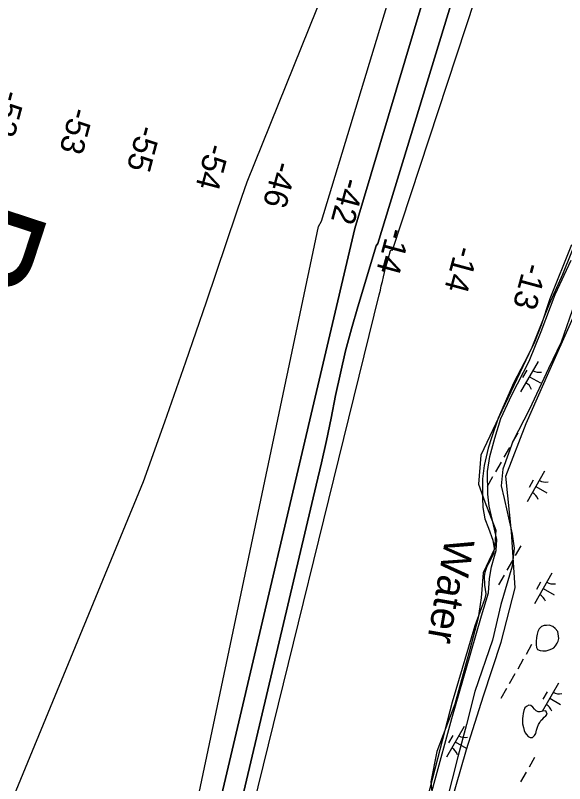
# Model space of a CAD drawing. Extents: x 3930721 to 3950824, y 220441 to 242861.
# Drawn here: x 3942447 to 3943227, y 233046 to 234136 of the extents above; entities that cross this region are included whole.
import ezdxf

# ---------------------------------------------------------------- set-up
doc = ezdxf.new("R2010")
doc.units = 0
for name, color, linetype in [('V-RIVR-EDGE', 7, 'Continuous'), ('V-RIVR-IDEN', 7, 'Continuous'), ('V-RIVR-JETY', 7, 'Continuous'), ('V-RIVR-RANG', 7, 'Continuous'), ('V-RRAP-FSHR', 7, 'Continuous'), ('V-TOPO-DPTH', 7, 'Continuous'), ('V-TOPO-MAJR', 7, 'Continuous'), ('V-TOPO-MINR', 7, 'Continuous'), ('V-TOPO-SHOR', 7, 'Continuous'), ('V-WETL-SWMP', 7, 'Continuous')]:
    doc.layers.add(name, color=color, linetype=linetype)

msp = doc.modelspace()

# ---------------------------------------------------------------- linework, layer by layer
at = {"layer": 'V-RIVR-EDGE'}
msp.add_lwpolyline([(3943285.6, 233921.8), (3943223.4, 233768.3), (3943204.5, 233725.8), (3943180.1, 233664.4), (3943107.7, 233511.7), (3943104.5, 233470.8), (3943113.2, 233445.6), (3943128.9, 233405.5), (3943127.3, 233378.7), (3943110.8, 233344.9), (3943108.4, 233309.4), (3943103.7, 233281.1), (3943091.9, 233236.2), (3943070.7, 233158.3), (3943045.5, 233091.4), (3943036.8, 233048.1), (3943039.2, 233024.5)], dxfattribs=at)
at = {"layer": 'V-RIVR-JETY'}
for points in [[(3943033.1, 233014.5), (3943041.4, 233046.4), (3943066.4, 233138.3), (3943093.4, 233231.4), (3943108.6, 233283.6), (3943118.4, 233316.3), (3943120.2, 233336.6), (3943122.8, 233353.3), (3943127.3, 233368.5), (3943129.4, 233376.3), (3943130.4, 233391.9), (3943125.6, 233413.1), (3943119.3, 233439.4), (3943117.5, 233456.6), (3943117.2, 233488.6), (3943120.6, 233510.1), (3943127.6, 233535.8), (3943136.1, 233563.8), (3943151.5, 233597.6), (3943176.3, 233645), (3943193.3, 233687.4), (3943213.1, 233739.9), (3943236.1, 233788.4)], [(3943241.1, 233728.1), (3943221.6, 233672.1), (3943203.9, 233634.8), (3943176.6, 233577), (3943153.3, 233531.2), (3943138.7, 233491.9), (3943136.4, 233468.1), (3943140.9, 233450.4), (3943144.9, 233431.6), (3943152.3, 233399.9), (3943154.8, 233379.9), (3943152.1, 233354.1), (3943136.2, 233300), (3943124.2, 233249.4), (3943099.4, 233176.6), (3943087.4, 233129.5), (3943075.1, 233083.9), (3943051.6, 232990.8)]]:
    msp.add_lwpolyline(points, dxfattribs=at)
at = {"layer": 'V-RRAP-FSHR'}
msp.add_lwpolyline([(3942882, 232404), (3942906.2, 232480.2), (3942929.5, 232556.7), (3942952.8, 232633.3), (3942976.5, 232709.8), (3942998.6, 232786.6), (3943020.8, 232863.4), (3943043, 232940.3), (3943065.2, 233017.2), (3943087.4, 233094.2), (3943111.4, 233170.3), (3943136.4, 233246.3), (3943156.6, 233323.6), (3943151.4, 233402.9), (3943143.4, 233482.1), (3943171.9, 233556.6), (3943204.4, 233629.7), (3943236.8, 233702.9), (3943268.8, 233776.2), (3943300.4, 233849.7), (3943331.9, 233923.2), (3943363.4, 233996.7), (3943394.9, 234070.3), (3943426.5, 234144)], dxfattribs=at)
at = {"layer": 'V-TOPO-DPTH'}
for points in [[(3942394.4, 231903.7), (3942586.2, 232551.5), (3942601, 232601.9), (3942615.5, 232652.3), (3942629.6, 232702.8), (3942643.5, 232753.3), (3942665.8, 232835.5), (3942668.3, 232845.1), (3942670.6, 232854.7), (3942672.5, 232864.3), (3942877.4, 233836.1), (3942881.5, 233844), (3943173.7, 234806.4)], [(3942394.4, 231903.7), (3942586.2, 232551.5), (3942601, 232601.9), (3942615.5, 232652.3), (3942629.6, 232702.8), (3942643.5, 232753.3), (3942665.8, 232835.5), (3942668.3, 232845.1), (3942670.6, 232854.7), (3942672.5, 232864.3), (3942877.4, 233836.1), (3942881.5, 233844), (3943173.7, 234806.4)], [(3943259.1, 234785.7), (3942961.5, 233812), (3942959.1, 233808.6), (3942933, 233722.4), (3942924, 233691.2), (3942915.7, 233659.8), (3942908.4, 233628.1), (3942901.7, 233596.3), (3942895.2, 233564.5), (3942888.6, 233532.6), (3942881.5, 233500.9), (3942874.2, 233469.2), (3942743, 232914.2), (3942734.1, 232877.2), (3942725, 232840.3), (3942715.6, 232803.4), (3942706, 232766.6), (3942520.9, 232068.2)], [(3942436.3, 231927), (3942493.1, 232113.6), (3942526.9, 232226.7), (3942560, 232340), (3942592, 232453.7), (3942623.2, 232567.6), (3942685.8, 232801.1), (3942691.8, 232824.3), (3942697.6, 232847.5), (3942702.9, 232870.9), (3942708, 232894.3), (3942929, 233833.4), (3943212.5, 234783.4)], [(3943212.5, 234783.4), (3942929, 233833.4), (3942708, 232894.3), (3942702.9, 232870.9), (3942697.6, 232847.5), (3942691.8, 232824.3), (3942685.8, 232801.1), (3942623.2, 232567.6), (3942592, 232453.7), (3942560, 232340), (3942526.9, 232226.7), (3942493.1, 232113.6), (3942436.3, 231927)]]:
    msp.add_lwpolyline(points, dxfattribs=at)
at = {"layer": 'V-TOPO-MAJR'}
msp.add_lwpolyline([(3942426.3, 232982), (3942628.9, 233474.4), (3942659.3, 233559.1), (3942689, 233644.1), (3942718.3, 233729.2), (3942761.1, 233855.8), (3942768.6, 233877.8), (3942776.2, 233899.7), (3943062.8, 234610.5)], dxfattribs=at)
at = {"layer": 'V-TOPO-MINR'}
for points in [[(3942394.4, 231903.7), (3942586.2, 232551.5), (3942601, 232601.9), (3942615.5, 232652.3), (3942629.6, 232702.8), (3942643.5, 232753.3), (3942665.8, 232835.5), (3942668.3, 232845.1), (3942670.6, 232854.7), (3942672.5, 232864.3), (3942877.4, 233836.1), (3942881.5, 233844), (3943173.7, 234806.4)], [(3942520.9, 232068.2), (3942706, 232766.6), (3942715.6, 232803.4), (3942725, 232840.3), (3942734.1, 232877.2), (3942743, 232914.2), (3942874.2, 233469.2), (3942881.5, 233500.9), (3942888.6, 233532.6), (3942895.2, 233564.5), (3942901.7, 233596.3), (3942908.4, 233628.1), (3942915.7, 233659.8), (3942924, 233691.2), (3942933, 233722.4), (3942959.1, 233808.6), (3942961.5, 233812), (3943259.1, 234785.7)], [(3942436.3, 231927), (3942493.1, 232113.6), (3942526.9, 232226.7), (3942560, 232340), (3942592, 232453.7), (3942623.2, 232567.6), (3942685.8, 232801.1), (3942691.8, 232824.3), (3942697.6, 232847.5), (3942702.9, 232870.9), (3942708, 232894.3), (3942929, 233833.4), (3943212.5, 234783.4)], [(3942763.3, 232925.7), (3942963.5, 233739.4), (3942965.1, 233745.7), (3942966.5, 233752), (3942968, 233758.3), (3942969.4, 233764.7), (3942970.9, 233771), (3942972.4, 233777.3), (3942974.2, 233783.5), (3942976, 233789.8), (3942979.7, 233802.1), (3942979.9, 233802.4), (3942980.1, 233802.6), (3942980.4, 233802.8), (3942981.6, 233802.9), (3942982.4, 233802.8), (3943295.2, 234752.4)]]:
    msp.add_lwpolyline(points, dxfattribs=at)
at = {"layer": 'V-TOPO-SHOR'}
for points in [[(3943217.1, 233261.6), (3943213.3, 233265.9), (3943210.1, 233268.7), (3943204.9, 233270.5), (3943201.1, 233270.2), (3943197.6, 233269.9), (3943193.7, 233268.6), (3943190.5, 233265.5), (3943188.7, 233261.7), (3943187.6, 233257.8), (3943186.9, 233253.3), (3943186.4, 233247.3), (3943186, 233242.8), (3943186.7, 233238.9), (3943188, 233236.1), (3943191.9, 233234.7), (3943195.7, 233234.3), (3943200.2, 233234.2), (3943204.8, 233235.6), (3943208.3, 233236.9), (3943211.1, 233238.6), (3943213.6, 233241.4), (3943216.1, 233244.8), (3943217.6, 233248), (3943218.3, 233251.5), (3943217.1, 233261.6)], [(3943199.8, 233148.9), (3943195.6, 233148.6), (3943192.1, 233147.6), (3943188.9, 233147.6), (3943186.2, 233149), (3943183.7, 233151.2), (3943181.7, 233154), (3943178.9, 233156.5), (3943175.8, 233156.9), (3943172.6, 233155.2), (3943170.1, 233153.4), (3943168.7, 233149.6), (3943167.9, 233145.1), (3943167.5, 233141.6), (3943166.8, 233138.1), (3943166.7, 233134.9), (3943167, 233130.7), (3943168.4, 233125.5), (3943169.4, 233120.9), (3943170.7, 233117.8), (3943172.4, 233115.3), (3943174.8, 233112.8), (3943177.6, 233111), (3943180.8, 233111.3), (3943184, 233114.1), (3943185.7, 233116.9), (3943186.5, 233121.4), (3943188, 233125.9), (3943189.4, 233129.4), (3943191.2, 233132.5), (3943193, 233135.3), (3943195.5, 233137.7), (3943197.6, 233140.1), (3943200.1, 233141.9), (3943201.9, 233144.3), (3943199.8, 233148.9)]]:
    msp.add_lwpolyline(points, dxfattribs=at)
at = {"layer": 'V-WETL-SWMP'}
for p, q in [((3943189, 233644.8), (3943164.2, 233601.5)), ((3943172.9, 233632.2), (3943166.9, 233621.8)), ((3943176.6, 233623.1), (3943192.2, 233614.2)), ((3943160.2, 233543.5), (3943152.3, 233529.6)), ((3943148.3, 233522.6), (3943140.3, 233508.8)), ((3943136.4, 233501.8), (3943128.4, 233487.9)), ((3943198.2, 233489), (3943173.3, 233445.6)), ((3943124.4, 233481), (3943116.5, 233467.1)), ((3943182.1, 233476.3), (3943176.1, 233465.9)), ((3943185.8, 233467.3), (3943201.4, 233458.3)), ((3943164.4, 233383.2), (3943156.5, 233369.4)), ((3943152.5, 233362.4), (3943144.5, 233348.5)), ((3943140.6, 233341.6), (3943132.6, 233327.7)), ((3943208.7, 233344.4), (3943183.8, 233301)), ((3943192.5, 233331.8), (3943186.6, 233321.3)), ((3943196.2, 233322.7), (3943211.9, 233313.8)), ((3943179.8, 233243), (3943171.9, 233229.1)), ((3943167.9, 233222.2), (3943160, 233208.3)), ((3943156, 233201.4), (3943148, 233187.5)), ((3943217.8, 233188.5), (3943194.8, 233148.3)), ((3943144.1, 233180.5), (3943136.1, 233166.7)), ((3943201.7, 233175.9), (3943195.7, 233165.5)), ((3943205.4, 233166.8), (3943221, 233157.9)), ((3943084, 233126.6), (3943059.1, 233083.2)), ((3943067.8, 233114), (3943061.9, 233103.6)), ((3943071.5, 233104.9), (3943087.1, 233096)), ((3943184, 233082.8), (3943176.1, 233068.9)), ((3943172.1, 233062), (3943164.1, 233048.1))]:
    msp.add_line(p, q, dxfattribs=at)
msp.add_lwpolyline([(3943236.6, 233810), (3943205.5, 233733.5), (3943193.1, 233696.1), (3943183.9, 233672.2), (3943174.5, 233652.7), (3943154.7, 233615.1), (3943132.2, 233564.2), (3943122.7, 233536.4), (3943118.1, 233521.6), (3943112.5, 233497.3), (3943110, 233478), (3943110, 233451.2), (3943110.6, 233437.6), (3943113.4, 233421.3), (3943118.5, 233408.2), (3943124.6, 233391), (3943126.7, 233379.4), (3943125.5, 233371.9), (3943120.9, 233362.3), (3943116.1, 233353.8), (3943113.5, 233345.5), (3943112.6, 233340), (3943112.7, 233327.3), (3943114.8, 233315.1), (3943113.6, 233308.2), (3943111, 233301.9), (3943108.1, 233294.2), (3943099.3, 233269.4), (3943067.1, 233161.2), (3943032.2, 233026.2)], dxfattribs=at)
for points in [[(3943217.1, 233261.6), (3943213.3, 233265.9), (3943210.1, 233268.7), (3943204.9, 233270.5), (3943201.1, 233270.2), (3943197.6, 233269.9), (3943193.7, 233268.6), (3943190.5, 233265.5), (3943188.7, 233261.7), (3943187.6, 233257.8), (3943186.9, 233253.3), (3943186.4, 233247.3), (3943186, 233242.8), (3943186.7, 233238.9), (3943188, 233236.1), (3943191.9, 233234.7), (3943195.7, 233234.3), (3943200.2, 233234.2), (3943204.8, 233235.6), (3943208.3, 233236.9), (3943211.1, 233238.6), (3943213.6, 233241.4), (3943216.1, 233244.8), (3943217.6, 233248), (3943218.3, 233251.5)], [(3943199.8, 233148.9), (3943195.6, 233148.6), (3943192.1, 233147.6), (3943188.9, 233147.6), (3943186.2, 233149), (3943183.7, 233151.2), (3943181.7, 233154), (3943178.9, 233156.5), (3943175.8, 233156.9), (3943172.6, 233155.2), (3943170.1, 233153.4), (3943168.7, 233149.6), (3943167.9, 233145.1), (3943167.5, 233141.6), (3943166.8, 233138.1), (3943166.7, 233134.9), (3943167, 233130.7), (3943168.4, 233125.5), (3943169.4, 233120.9), (3943170.7, 233117.8), (3943172.4, 233115.3), (3943174.8, 233112.8), (3943177.6, 233111), (3943180.8, 233111.3), (3943184, 233114.1), (3943185.7, 233116.9), (3943186.5, 233121.4), (3943188, 233125.9), (3943189.4, 233129.4), (3943191.2, 233132.5), (3943193, 233135.3), (3943195.5, 233137.7), (3943197.6, 233140.1), (3943200.1, 233141.9), (3943201.9, 233144.3)]]:
    msp.add_lwpolyline(points, close=True, dxfattribs=at)
for centre, start, end in [((3943190.6, 233647), 239.4279, 280.9715), ((3943163.1, 233599.1), 19.4279, 60.9715), ((3943199.7, 233491.1), 239.4279, 280.9715), ((3943172.3, 233443.2), 19.4279, 60.9715), ((3943210.2, 233346.6), 239.4279, 280.9715), ((3943182.7, 233298.6), 19.4279, 60.9715), ((3943219.3, 233190.7), 239.4279, 280.9715), ((3943191.9, 233142.7), 19.4279, 60.9715), ((3943085.5, 233128.8), 239.4279, 280.9715), ((3943058, 233080.9), 19.4279, 60.9715)]:
    msp.add_arc(centre, 17.6, start, end, dxfattribs=at)

# ---------------------------------------------------------------- texts
at = {"layer": 'V-RIVR-IDEN'}
for s, height, rotation, p in [('PASS', 150, 251.8215, (3942353.6, 233903.4)), ('Water', 42, 259.9589, (3943057.6, 233396.3))]:
    msp.add_text(s, height=height, rotation=rotation, dxfattribs=at).set_placement(p)
at = {"layer": 'V-RIVR-RANG'}
for s, rotation, p in [('-53', 255.0529, (3942429.5, 234031.4)), ('-53', 255.0529, (3942526.2, 234006.8)), ('-55', 255.0529, (3942621.6, 233981.6)), ('-54', 255.0529, (3942719.4, 233955.8)), ('-46', 255.0529, (3942814.9, 233930.5)), ('-42', 255.0529, (3942911.4, 233907.2)), ('-14', 254.9083, (3942976, 233836.2)), ('-14', 254.9083, (3943072.6, 233810.4)), ('-13', 254.9083, (3943169.7, 233786.3))]:
    msp.add_text(s, height=33.5, rotation=rotation, dxfattribs=at).set_placement(p)

doc.saveas('drawing.dxf')
